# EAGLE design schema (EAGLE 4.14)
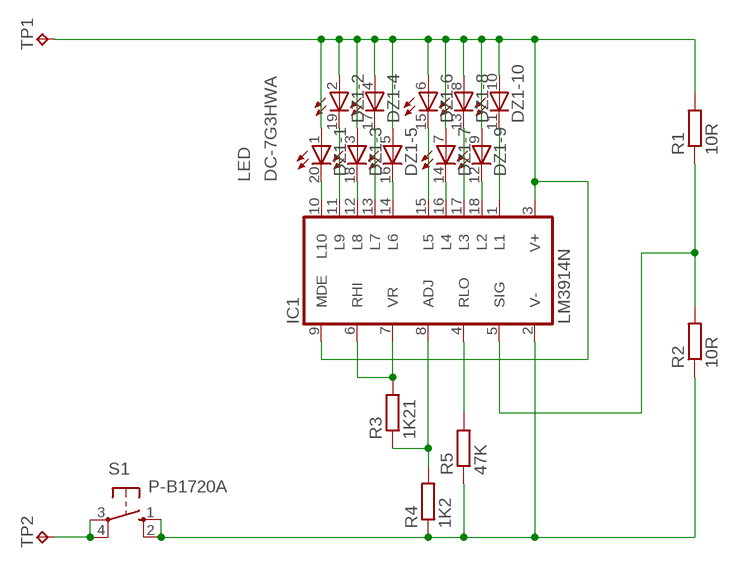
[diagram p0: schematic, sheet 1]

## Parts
DZ1  LB10  [LB10]
IC1  LM3914N  [DIL18]
R1  10R  R-EU_0204/7  [0204/7]
R2  10R  R-EU_0204/7  [0204/7]
R3  1K21  R-EU_0204/7  [0204/7]
R4  1K2  R-EU_0204/7  [0204/7]
R5  47K  R-EU_0204/7  [0204/7]
S1  P-B1720A  10-XX  [B3F-10XX]
TP1  TPPAD1-17Y  [P1-17Y]
TP2  TPPAD1-17Y  [P1-17Y]

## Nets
N$1: DZ1.11(-10:C) IC1.1(L1)
N$2: DZ1.12(-9:C) IC1.18(L2)
N$3: DZ1.13(-8:C) IC1.17(L3)
N$4: DZ1.14(-7:C) IC1.16(L4)
N$5: DZ1.15(-6:C) IC1.15(L5)
N$6: DZ1.16(-5:C) IC1.14(L6)
N$7: DZ1.17(-4:C) IC1.13(L7)
N$8: DZ1.18(-3:C) IC1.12(L8)
N$9: DZ1.19(-2:C) IC1.11(L9)
N$10: DZ1.20(-1:C) IC1.10(L10)
N$11: S1.3(P) S1.4(P1) TP2.1(TP)
N$12: DZ1.1(-1:A) DZ1.2(-2:A) DZ1.3(-3:A) DZ1.4(-4:A) DZ1.5(-5:A) DZ1.6(-6:A) DZ1.7(-7:A) DZ1.8(-8:A) DZ1.9(-9:A) DZ1.10(-10:A) IC1.3(V+) IC1.9(MDE) R1.2 TP1.1(TP)
N$13: IC1.8(ADJ) R3.1 R4.2
N$15: IC1.6(RHI) IC1.7(VR) R3.2
N$16: IC1.5(SIG) R1.1 R2.2
N$17: IC1.4(RLO) R5.2
N$18: IC1.2(V-) R2.1 R4.1 R5.1 S1.1(S) S1.2(S1)

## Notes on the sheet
- LED | DC-7G3HWA

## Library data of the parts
DZ1 = led:LB10: LED BLOCK 10-LED bar graph, DIL, Siemens
IC1 = linear:LM3914N: LED DRIVER senses analog voltage levels and drives 10 LEDs
R1-R5 = rcl:R-EU_: RESISTOR, European symbol
S1 = switch-omron:10-XX: OMRON SWITCH
TP1 TP2 = testpad:TP

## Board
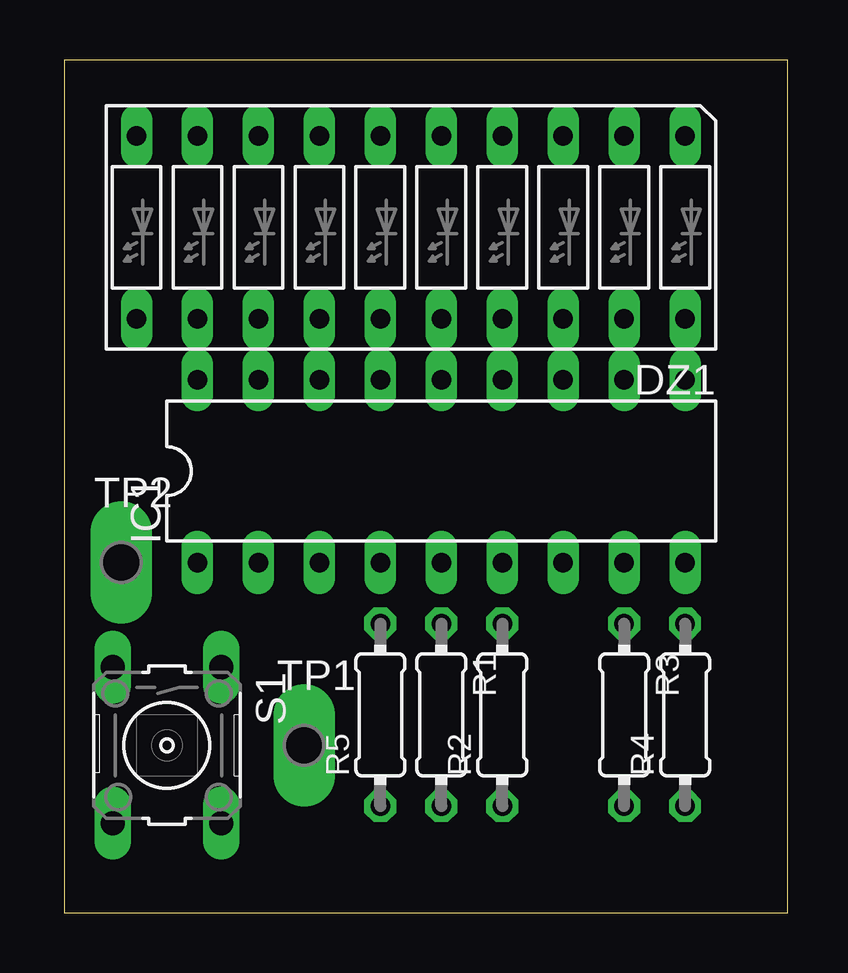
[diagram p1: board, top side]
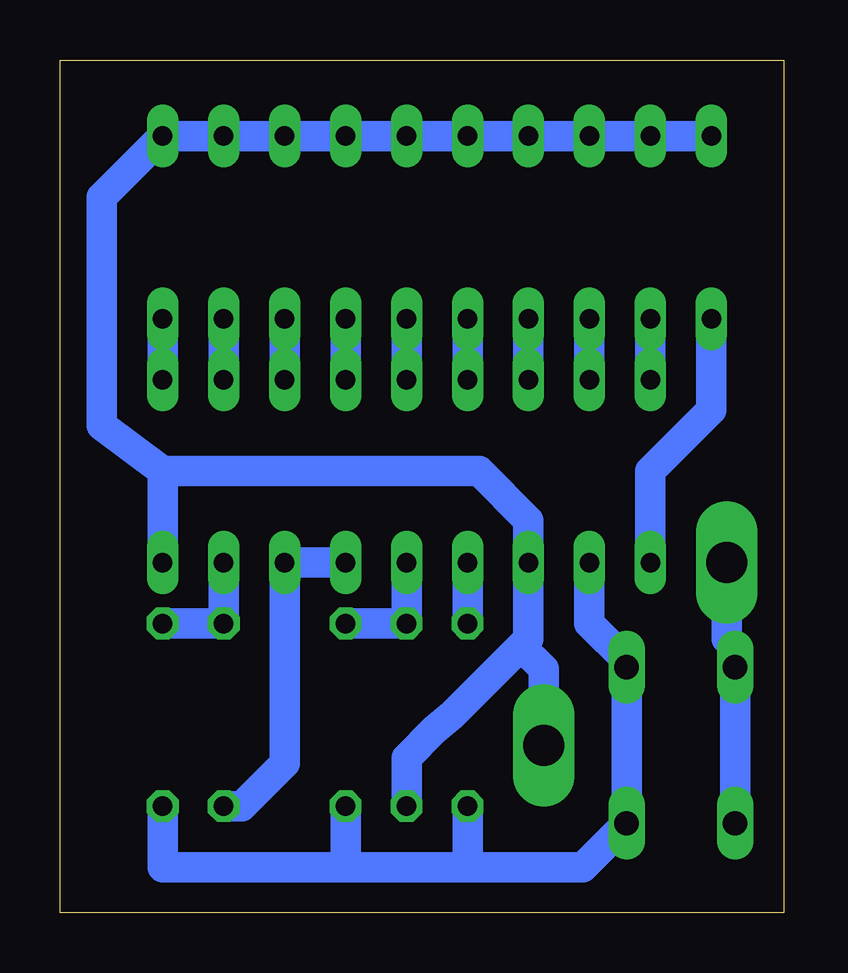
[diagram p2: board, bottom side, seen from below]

Size 30.15 x 35.55 mm. Coordinates in mm from the lower left corner, seen from the top.
Outline: 0,0 30.15,0 30.15,35.55 0,35.55 0,0
Copper layers (1*16): Top 0.035mm / dielectric 1.5mm / Bottom 0.035mm
Design rules "default": minimum track width 10mil, minimum drill 24mil, track to track 8mil, track to pad 8mil, pad to pad 8mil, via to via 8mil, smd to smd 8mil, copper to edge 40mil, drill to drill 8mil, minimum pad ring 10mil, minimum via ring 8mil, stop-mask expansion 4mil, vias tented up to drill 0mil, thermal gap 10mil

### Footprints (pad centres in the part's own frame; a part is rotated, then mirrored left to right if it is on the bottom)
LB10 = drill 0.813 long: 1 -11.43,-3.81; 2 -8.89,-3.81; 3 -6.35,-3.81; 4 -3.81,-3.81; 5 -1.27,-3.81; 6 1.27,-3.81; 7 3.81,-3.81; 8 6.35,-3.81; 9 8.89,-3.81; 10 11.43,-3.81; 11 11.43,3.81; 12 8.89,3.81; 13 6.35,3.81; 14 3.81,3.81; 15 1.27,3.81; 16 -1.27,3.81; 17 -3.81,3.81; 18 -6.35,3.81; 19 -8.89,3.81; 20 -11.43,3.81
DIL18 = drill 0.813 long: 1 -10.16,-3.81; 2 -7.62,-3.81; 3 -5.08,-3.81; 4 -2.54,-3.81; 5 0,-3.81; 6 2.54,-3.81; 7 5.08,-3.81; 8 7.62,-3.81; 9 10.16,-3.81; 10 10.16,3.81; 11 7.62,3.81; 12 5.08,3.81; 13 2.54,3.81; 14 0,3.81; 15 -2.54,3.81; 16 -5.08,3.81; 17 -7.62,3.81; 18 -10.16,3.81
0204/7 = drill 0.813 octagon: 1 -3.81,0; 2 3.81,0
B3F-10XX = drill 1.016 long: 1 -3.251,2.261; 2 3.251,2.261; 3 -3.251,-2.261; 4 3.251,-2.261
P1-17Y = drill 1.702 pad 2.121 long: 1 0,0

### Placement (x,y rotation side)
DZ1  14.44,28.57 180 top
IC1  15.71,18.41 0 top
R1  15.71,8.25 270 top
R2  18.25,8.25 90 top
R3  23.33,8.25 270 top
R4  25.87,8.25 90 top
R5  13.17,8.25 90 top
S1  4.28,6.98 270 top
TP1  10,6.98 0 top
TP2  2.38,14.6 0 top

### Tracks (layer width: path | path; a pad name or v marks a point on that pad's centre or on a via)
N$1
  Bottom 1.27: IC1.1 5.55,18.41 3.01,20.95 DZ1.11
N$2
  Bottom 1.27: IC1.18 DZ1.12
N$3
  Bottom 1.27: IC1.17 DZ1.13
N$4
  Bottom 1.27: IC1.16 DZ1.14
N$5
  Bottom 1.27: IC1.15 DZ1.15
N$6
  Bottom 1.27: IC1.14 DZ1.16
N$7
  Bottom 1.27: IC1.13 DZ1.17
N$8
  Bottom 1.27: IC1.12 DZ1.18
N$9
  Bottom 1.27: IC1.11 DZ1.19
N$10
  Bottom 1.27: IC1.10 DZ1.20
N$11
  Bottom 1.27: S1.4 S1.3 2.02,11.07 2.38,11.43 TP2.1
N$12
  Bottom 1.27: DZ1.10 DZ1.9 DZ1.8 DZ1.7 DZ1.6 DZ1.5 DZ1.4 DZ1.3 DZ1.2 DZ1.1 28.41,29.84 28.41,20.31 25.87,18.41 | 25.87,18.41 IC1.9 | 25.87,18.41 12.69,18.41 10.63,16.36 IC1.3 10.63,11.43 10.95,11.11 | R1.2 15.71,6.45 14.55,7.62 13.81,8.25 10.95,11.11 | TP1.1 10,10.16 10.95,11.11
N$13
  Bottom 1.27: IC1.8 R3.1 R4.2
N$15
  Bottom 1.27: IC1.6 IC1.7 20.79,6.24 22.59,4.44 R3.2
N$16
  Bottom 1.27: R2.2 R1.1 IC1.5
N$17
  Bottom 1.27: R5.2 IC1.4
N$18
  Bottom 1.27: 18.25,1.9 R2.1 | 13.17,1.9 18.25,1.9 | R4.1 25.87,1.9 18.25,1.9 | 13.17,1.9 R5.1 | IC1.2 8.09,12.06 6.54,10.51 S1.1 S1.2 8.37,1.9 13.17,1.9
